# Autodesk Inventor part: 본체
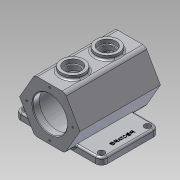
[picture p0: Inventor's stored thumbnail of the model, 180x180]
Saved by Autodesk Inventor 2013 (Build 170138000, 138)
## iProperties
Created: 2021-06
Part Number: 본체
Material: 알루미늄 6061
Document SubType Name: Modeling
Designer: max6
Density: 2.71 g/cm^3
Mass: 1497.87 g
Surface Area: 1110.26 cm^2
Volume: 552.721 cm^3
Author: max6
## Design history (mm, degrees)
sketch "스케치1" dims "d2" = 105
  geometry: L1 (26.25, -45.466)-(-26.25, -45.466); L2 (-26.25, -45.466)-(-52.5, 0); L3 (-52.5, 0)-(-26.25, 45.466); L4 (-26.25, 45.466)-(26.25, 45.466); L5 (26.25, 45.466)-(52.5, 0); L6 (52.5, 0)-(26.25, -45.466); 3 further points
  constraints: 12 end point, 2 coincident, 1 horizontal, 16 other
extrude "돌출1" new body sketch "스케치1" stored distance "d4" = 140; taper "d5" = 0 deg
node "작업 평면1"
sketch "스케치2"
  geometry: L1 (0, -98)-(0, 98) reference; L2 (-73.5, 0)-(73.5, 0) reference; L3 (-75, -55)-(75, -55); L4 (75, -55)-(75, 45); L5 (75, 45)-(-75, 45); L6 (-75, 45)-(-75, -55); L7 (-75, -55)-(75, 45); L8 (75, -55)-(-75, 45); L9 (-26.25, -70)-(-52.5, -70) reference; L10 (26.25, 70)-(52.5, 70) reference; 1 further point
  constraints: 12 end point, 2 midpoint, 2 parallel, 1 horizontal, 1 perpendicular, 1 point on line
  dimensions: "d12" = 150 distance of L4.end L5.end; "d13" = 15 distance between parallel lines of L9 L3; "d14" = 25 distance between parallel lines of L10 L5
extrude "돌출2" join sketch "스케치2" distance "d15" = 12; taper "d16" = 0 deg
sketch "스케치5"
  geometry: C1 r 30 at (0, 0); 1 further point
  constraints: 1 centre point, 1 coincident
  dimensions: "d33" = 60 diameter of C1
extrude "돌출3" cut sketch "스케치5" distance "d35" = 12; taper "d36" = 0 deg
sketch "스케치6"
  geometry: C1 r 30 at (0, 0); 1 further point
  constraints: 1 centre point, 1 coincident
  dimensions: "d37" = 60 diameter of C1
extrude "돌출4" cut sketch "스케치6" distance "d39" = 12; taper "d40" = 0 deg
sketch "스케치7"
  geometry: C1 r 30 at (0, 0) reference; C2 r 37.5 at (0, 0)
  constraints: 1 centre point, 1 coincident
  dimensions: "d41" = 75 diameter of C2
extrude "돌출5" cut sketch "스케치7" distance "d43" = 116; taper "d44" = 0 deg
node "작업 평면2"
sketch "스케치8"
  geometry: L1 (0, -98)-(0, 98) reference; L2 (-105, 0)-(105, 0) reference; L3 (26.25, -70)-(-26.25, -70) reference; L4 (-26.25, 70)-(26.25, 70) reference; C1 r 20 at (0, -30); C2 r 20 at (0, 30); 1 further point
  constraints: 2 centre point, 2 point on line
  dimensions: "d46" = 40 diameter of C1; "d48" = 40 diameter of C2; "d50" = 60 distance of C2.centre C1.centre; "d131" = 40 distance from line of L4 C2.centre
extrude "돌출6" join sketch "스케치8" stored distance "d51" = 116; taper "d52" = 0 deg
sketch "스케치9"
  geometry: C1 r 20 at (0, 0) reference; C2 r 15 at (0, 0); C3 r 20 at (0, 60) reference; C4 r 15 at (0, 60); 1 further point
  constraints: 2 centre point, 2 coincident
  dimensions: "d53" = 30 diameter of C2; "d55" = 30 diameter of C4
extrude "돌출7" cut sketch "스케치9" distance "d56" = 8; taper "d57" = 0 deg
sketch "스케치10"
  geometry: C1 r 15 at (0, 0) reference; C2 r 15 at (0, 60) reference; C3 r 12.5 at (0, 0); C4 r 12.5 at (0, 60); 1 further point
  constraints: 2 centre point, 2 coincident
  dimensions: "d58" = 25 diameter of C3; "d60" = 25 diameter of C4
extrude "돌출8" cut sketch "스케치10" stored distance "d61" = 8; taper "d62" = 0 deg
fillet "모깎기1" dims "d90" = 10
sketch "스케치14"
  geometry: L1 (65, 45)-(-65, 45) reference; L2 (75, -45)-(75, 35) reference; L3 (-65, -55)-(65, -55) reference; L4 (-75, 35)-(-75, -45) reference; C1 r 5.5 at (-65, -45); C2 r 5.5 at (-65, 35); C3 r 5.5 at (65, 35); C4 r 5.5 at (65, -45); A1 r 10 centre (-65, 35) between (-65, 45) and (-75, 35) reference; A2 r 10 centre (65, 35) between (75, 35) and (65, 45) reference; A3 r 10 centre (65, -45) between (65, -55) and (75, -45) reference; A4 r 10 centre (-65, -45) between (-75, -45) and (-65, -55) reference; 1 further point
  constraints: 4 centre point, 4 coincident
  dimensions: "d91" = 11 diameter of C1; "d93" = 11 diameter of C2; "d94" = 11 diameter of C4; "d95" = 11 diameter of C3
extrude "돌출9" cut sketch "스케치14" stored distance "d96" = 8; taper "d97" = 0 deg
fillet "모깎기2" dims "d98" = 8
fillet "모깎기3" dims "d99" = 5
fillet "모깎기4" dims "d100" = 3
chamfer "모따기1" distance "d101" = 1; stored, may be unused: second distance "d102" = 2, angle "d103" = 45 deg
sketch "스케치15" dims "d104" = 80
  geometry: L1 (-105, 0)-(105, 0) reference; L2 (0, 70.5)-(0, -73) reference; L3 (0, 0)-(28.284, -28.284); C1 r 31 at (0, 0) reference; 1 further point
  constraints: 2 coincident, 2 end point, 3 other
  dimensions: "d106" = 45 deg angle of L2 L3
hole "구멍3" sketch "스케치15" at (28.284, -28.284) diameter "d108" = 3.242; stored, may be unused: countersink angle "d112" = 90 deg, drill point angle "d114" = 118 deg; dims "d109" = 8, "d110" = 4, "d111" = 2, "d113" = 10
sketch "스케치16"
  geometry: L1 (-105, 0)-(105, 0) reference; L2 (0, -70.5)-(0, 73) reference; C1 r 31 at (0, 0) reference; A1 r 40 centre (0, 0) between (0, 40) and (40, 0); 2 further points
  constraints: 4 point on circle, 4 point on line, 1 centre point, 1 coincident
  dimensions: "d118" = 80 diameter of A1
hole "구멍4" sketch "스케치16" at (0, 40), (40, 0), (0, -40), (-40, 0) diameter "d120" = 3.242; stored, may be unused: countersink angle "d124" = 90 deg, drill point angle "d126" = 118 deg; dims "d121" = 8, "d122" = 4, "d123" = 2, "d125" = 10
sketch "스케치17"
  geometry: L1 (75, -45)-(75, 35) reference; L2 (65, 45)-(32.293, 45) reference; 2 further points
  constraints: 1 other
  dimensions: "d127" = 14 distance from line of L1 point (61, -5); "d128" = 50 distance from line of L2 point (61, -5)
feature "엠보싱2" sketch "스케치17" dims "d2" = 105, "d15" = 12, "d129" = 0.5, "d130" = 0
node "솔리드1"
pattern_circular "원형 패턴2" dims angle "d116" = 360 deg
node "투영된 루프1"
node "투영된 루프2"
node "투영된 루프3"
other parameters: "d45" = 52.5
